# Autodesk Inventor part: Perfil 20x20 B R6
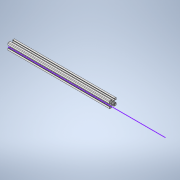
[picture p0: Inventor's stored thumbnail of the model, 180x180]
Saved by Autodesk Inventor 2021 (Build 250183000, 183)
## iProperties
Created: 2020-12
Part Number: Perfil 20x20 B R6
Material: Genérico
Document SubType Name: Modeling
Designer: ATOUZA
Density: 1 g/cm^3
Appearance: Valor por defecto
Author: ATOUZA
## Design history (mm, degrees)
sketch "Boceto1"
  geometry: L1 (4.5, 0.954)-(4.5, 3.232); L2 (4.646, 3.586)-(6.914, 5.854); L3 (7.268, 6)-(8, 6); L4 (8.5, 5.5)-(8.5, 3.6); L5 (9, 3.1)-(9.3, 3.1); L6 (9.5, 3.3)-(9.5, 3.65); L7 (9.5, 3.65)-(9.8, 3.65); L8 (10, 3.85)-(10, 8.5); L9 (8.5, 10)-(3.85, 10); L10 (3.65, 9.8)-(3.65, 9.5); L11 (3.65, 9.5)-(3.3, 9.5); L12 (3.1, 9.3)-(3.1, 9); L13 (3.6, 8.5)-(5.5, 8.5); L14 (6, 8)-(6, 7.268); L15 (5.854, 6.914)-(3.586, 4.646); L16 (3.232, 4.5)-(0.954, 4.5); L17 (0.854, 4.473)-(0.1, 4.038); L18 (-0.1, 4.038)-(-0.854, 4.473); L19 (-0.954, 4.5)-(-3.232, 4.5); L20 (-3.586, 4.646)-(-5.854, 6.914); L21 (-6, 7.268)-(-6, 8); L22 (-5.5, 8.5)-(-3.6, 8.5); L23 (-3.1, 9)-(-3.1, 9.3); L24 (-3.3, 9.5)-(-3.65, 9.5); L25 (-3.65, 9.5)-(-3.65, 9.8); L26 (-3.85, 10)-(-8.5, 10); L27 (-10, 8.5)-(-10, 3.85); L28 (-9.8, 3.65)-(-9.5, 3.65); L29 (-9.5, 3.65)-(-9.5, 3.3); L30 (-9.3, 3.1)-(-9, 3.1); L31 (-8.5, 3.6)-(-8.5, 5.5); L32 (-8, 6)-(-7.268, 6); L33 (-6.914, 5.854)-(-4.646, 3.586); L34 (-4.5, 3.232)-(-4.5, 0.954); L35 (-4.473, 0.854)-(-4.038, 0.1); L36 (-4.038, -0.1)-(-4.473, -0.854); L37 (-4.5, -0.954)-(-4.5, -3.232); L38 (-4.646, -3.586)-(-6.914, -5.854); L39 (-7.268, -6)-(-8, -6); L40 (-8.5, -5.5)-(-8.5, -3.6); L41 (-9, -3.1)-(-9.3, -3.1); L42 (-9.5, -3.3)-(-9.5, -3.65); L43 (-9.5, -3.65)-(-9.8, -3.65); L44 (-10, -3.85)-(-10, -8.5); L45 (-8.5, -10)-(-3.85, -10); L46 (-3.65, -9.8)-(-3.65, -9.5); L47 (-3.65, -9.5)-(-3.3, -9.5); L48 (-3.1, -9.3)-(-3.1, -9); L49 (-3.6, -8.5)-(-5.5, -8.5); L50 (-6, -8)-(-6, -7.268); L51 (-5.854, -6.914)-(-3.586, -4.646); L52 (-3.232, -4.5)-(-0.954, -4.5); L53 (1.258, -2.445)-(1.914, -2.99); L54 (2.992, -1.91)-(2.445, -1.258); L55 (2.445, 1.258)-(2.992, 1.91); L56 (1.914, 2.99)-(1.258, 2.445); L57 (-1.258, 2.445)-(-1.914, 2.99); L58 (-2.992, 1.91)-(-2.445, 1.258); L59 (-2.445, -1.258)-(-2.992, -1.91); L60 (-1.914, -2.99)-(-1.258, -2.445); L61 (1.258, -2.445)-(1.914, -2.99); L62 (2.992, -1.91)-(2.445, -1.258); L63 (2.445, 1.258)-(2.992, 1.91); L64 (1.914, 2.99)-(1.258, 2.445)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; A1 r 0.5 centre (5, 3.232) between (4.646, 3.586) and (4.5, 3.232); A2 r 0.5 centre (7.268, 5.5) between (7.268, 6) and (6.914, 5.854); A3 r 0.5 centre (8, 5.5) between (8.5, 5.5) and (8, 6); A4 r 0.5 centre (9, 3.6) between (8.5, 3.6) and (9, 3.1); A5 r 0.2 centre (9.3, 3.3) between (9.3, 3.1) and (9.5, 3.3); A6 r 0.2 centre (9.8, 3.85) between (9.8, 3.65) and (10, 3.85); A7 r 1.5 centre (8.5, 8.5) between (10, 8.5) and (8.5, 10); A8 r 0.2 centre (3.85, 9.8) between (3.85, 10) and (3.65, 9.8); A9 r 0.2 centre (3.3, 9.3) between (3.3, 9.5) and (3.1, 9.3); A10 r 0.5 centre (3.6, 9) between (3.1, 9) and (3.6, 8.5); A11 r 0.5 centre (5.5, 8) between (6, 8) and (5.5, 8.5); A12 r 0.5 centre (5.5, 7.268) between (5.854, 6.914) and (6, 7.268); A13 r 0.5 centre (3.232, 5) between (3.232, 4.5) and (3.586, 4.646); A14 r 0.2 centre (0.954, 4.3) between (0.954, 4.5) and (0.854, 4.473); A15 r 0.2 centre (0, 4.211) between (-0.1, 4.038) and (0.1, 4.038); A16 r 0.2 centre (-0.954, 4.3) between (-0.854, 4.473) and (-0.954, 4.5); A17 r 0.5 centre (-3.232, 5) between (-3.586, 4.646) and (-3.232, 4.5); A18 r 0.5 centre (-5.5, 7.268) between (-6, 7.268) and (-5.854, 6.914); A19 r 0.5 centre (-5.5, 8) between (-5.5, 8.5) and (-6, 8); A20 r 0.5 centre (-3.6, 9) between (-3.6, 8.5) and (-3.1, 9); A21 r 0.2 centre (-3.3, 9.3) between (-3.1, 9.3) and (-3.3, 9.5); A22 r 0.2 centre (-3.85, 9.8) between (-3.65, 9.8) and (-3.85, 10); A23 r 1.5 centre (-8.5, 8.5) between (-8.5, 10) and (-10, 8.5); A24 r 0.2 centre (-9.8, 3.85) between (-10, 3.85) and (-9.8, 3.65); A25 r 0.2 centre (-9.3, 3.3) between (-9.5, 3.3) and (-9.3, 3.1); A26 r 0.5 centre (-9, 3.6) between (-9, 3.1) and (-8.5, 3.6); A27 r 0.5 centre (-8, 5.5) between (-8, 6) and (-8.5, 5.5); A28 r 0.5 centre (-7.268, 5.5) between (-6.914, 5.854) and (-7.268, 6); A29 r 0.5 centre (-5, 3.232) between (-4.5, 3.232) and (-4.646, 3.586); A30 r 0.2 centre (-4.3, 0.954) between (-4.5, 0.954) and (-4.473, 0.854); A31 r 0.2 centre (-4.211, 0) between (-4.038, -0.1) and (-4.038, 0.1); A32 r 0.2 centre (-4.3, -0.954) between (-4.473, -0.854) and (-4.5, -0.954); A33 r 0.5 centre (-5, -3.232) between (-4.646, -3.586) and (-4.5, -3.232); A34 r 0.5 centre (-7.268, -5.5) between (-7.268, -6) and (-6.914, -5.854); A35 r 0.5 centre (-8, -5.5) between (-8.5, -5.5) and (-8, -6); A36 r 0.5 centre (-9, -3.6) between (-8.5, -3.6) and (-9, -3.1); A37 r 0.2 centre (-9.3, -3.3) between (-9.3, -3.1) and (-9.5, -3.3); A38 r 0.2 centre (-9.8, -3.85) between (-9.8, -3.65) and (-10, -3.85); A39 r 1.5 centre (-8.5, -8.5) between (-10, -8.5) and (-8.5, -10); A40 r 0.2 centre (-3.85, -9.8) between (-3.85, -10) and (-3.65, -9.8); A41 r 0.2 centre (-3.3, -9.3) between (-3.3, -9.5) and (-3.1, -9.3); A42 r 0.5 centre (-3.6, -9) between (-3.1, -9) and (-3.6, -8.5); A43 r 0.5 centre (-5.5, -8) between (-6, -8) and (-5.5, -8.5); A44 r 0.5 centre (-5.5, -7.268) between (-5.854, -6.914) and (-6, -7.268); A45 r 0.5 centre (-3.232, -5) between (-3.232, -4.5) and (-3.586, -4.646); A46 r 2.75 centre (0, 0) between (-1.258, -2.445) and (1.258, -2.445); A47 r 3.55 centre (0, 0) between (1.914, -2.99) and (2.992, -1.91); A48 r 2.75 centre (0, 0) between (2.445, -1.258) and (2.445, 1.258); A49 r 3.55 centre (0, 0) between (2.992, 1.91) and (1.914, 2.99); A50 r 2.75 centre (0, 0) between (1.258, 2.445) and (-1.258, 2.445); A51 r 3.55 centre (0, 0) between (-1.914, 2.99) and (-2.992, 1.91); A52 r 2.75 centre (0, 0) between (-2.445, 1.258) and (-2.445, -1.258); A53 r 3.55 centre (0, 0) between (-2.992, -1.91) and (-1.914, -2.99); A54 r 2.75 centre (0, 0) between (-1.258, -2.445) and (1.258, -2.445); A55 r 3.55 centre (0, 0) between (1.914, -2.99) and (2.992, -1.91); A56 r 2.75 centre (0, 0) between (2.445, -1.258) and (2.445, 1.258); A57 r 3.55 centre (0, 0) between (2.992, 1.91) and (1.914, 2.99); A58 r 2.75 centre (0, 0) between (1.258, 2.445) and (-1.258, 2.445); A59 r 3.55 centre (0, 0) between (-1.914, 2.99) and (-2.992, 1.91); A60 r 2.75 centre (0, 0) between (-2.445, 1.258) and (-2.445, -1.258); A61 r 3.55 centre (0, 0) between (-2.992, -1.91) and (-1.914, -2.99); A62 r 0.5 centre (-8, -5.5) between (-8.5, -5.5) and (-8, -6); A63 r 0.2 centre (-4.211, 0) between (-4.038, -0.1) and (-4.038, 0.1); A64 r 0.5 centre (-7.268, 5.5) between (-6.914, 5.854) and (-7.268, 6)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; 1 further point
  constraints: 324 end point, 198 point on circle, 99 centre point, 2 point on line, 6 other
extrude "Extrusión1" new body sketch "Boceto1" distance "d0" = 290; taper "d1" = 0 deg
node "Sólido1"
sketch "Boceto5"
  geometry: L1 (0, -3.85)-(289.978, -3.85)
  constraints: 2 end point, 1 horizontal
